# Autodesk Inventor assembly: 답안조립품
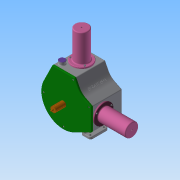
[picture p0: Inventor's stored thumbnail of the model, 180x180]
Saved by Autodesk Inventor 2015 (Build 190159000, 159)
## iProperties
Created: 2022-01
Part Number: 답안조립품
Document SubType Name: Assembly
Designer: user
Mass: 3748.65 g
Surface Area: 4101.79 cm^2
Volume: 1119.43 cm^3
Density: 3.34873 g/cm^3
Author: user
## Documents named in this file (13)
- C:\Users\user\Desktop\620117V1009\답안조립품.iam
- C:\Users\user\Desktop\620117V1009\너트 M3.ipt
- C:\Users\user\Desktop\620117V1009\베어링 20 x 37 x 9.ipt
- C:\Users\user\Desktop\620117V1009\본체.ipt
- C:\Users\user\Desktop\620117V1009\볼트 M3 x 12.ipt
- C:\Users\user\Desktop\620117V1009\실린더.ipt
- C:\Users\user\Desktop\620117V1009\앞커버.ipt
- C:\Users\user\Desktop\620117V1009\축.ipt
- C:\Users\user\Desktop\620117V1009\측정게이지.ipt
- C:\Users\user\Desktop\620117V1009\커넥팅로드 캡.ipt
- C:\Users\user\Desktop\620117V1009\커넥팅로드.ipt
- C:\Users\user\Desktop\620117V1009\피스톤 핀.ipt
- C:\Users\user\Desktop\620117V1009\피스톤.ipt
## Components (4 placed, 2 different names)
1. 피스톤 핀:1
2. 피스톤:1
3. 피스톤:2
4. 피스톤 핀:2
